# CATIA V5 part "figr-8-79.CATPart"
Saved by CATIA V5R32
Part number: Part1
Bounding box of the stored display mesh (mm): x -35 to 35, y -116.369 to 116.369, z 0 to 117.647
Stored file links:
  D:\PROJECTS\Project 2022\CATIA V5 6R 2022\Resources\Part Files\c08_catia_v5_6r2022_prt\figr-8-79.CATPart
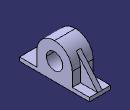
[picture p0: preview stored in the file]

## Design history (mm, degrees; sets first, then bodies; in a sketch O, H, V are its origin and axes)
Body1 (main body)
  Sketch1 on yz-plane, origin (0, 0, 0), H (0, 1, 0), V (0, 0, 1)
    line L1 (0, 0) -> (116.3687, 0)
    point P1 (116.3687, 0)
    line L2 (116.3687, 0) -> (116.3687, 12.5279)
    point P2 (116.3687, 12.5279)
    line L3 (116.3687, 12.5279) -> (58.943, 12.5279)
    point P3 (58.943, 12.5279)
    line L4 (58.943, 12.5279) -> (58.943, 58.7038)
    point P4 (58.943, 58.7038)
    arc A1 centre (0, 58.7038) radius 58.943 from (58.943, 58.7038) to (0, 117.6467) ccw
    point P5 (0, 58.7038)
    point P6 (-58.943, 58.7038)
    line L5 (-58.943, 58.7038) -> (-58.943, 12.5279)
    point P7 (-58.943, 12.5279)
    axis line L6 (0, 0) -> (0, 108.1111)
    point P9 (0, 117.6467)
    point P10 (0, 117.6467)
    point P11 (-58.943, 58.7038)
    arc A2 centre (0, 58.7038) radius 58.943 from (-58.943, 58.7038) to (0, 117.6467) cw
    point P13 (-58.943, 12.5279)
    point P14 (-116.3687, 12.5279)
    line L7 (-116.3687, 12.5279) -> (-58.943, 12.5279)
    point P15 (-116.3687, 0)
    line L8 (-116.3687, 0) -> (-116.3687, 12.5279)
    point P16 (0, 0)
    line L9 (0, 0) -> (-116.3687, 0)
    circle A3 centre (0, 58.7038) radius 27.1825
    horizontal: L1 H, L3 H
    vertical: L2 V, L4 V, L6 V
    tangency: A1 L4, L5 A1
    coincidence: P7 L3, P5 V, L6 P9, P6 P11, O P16, P9 P10, P7 P13
    symmetry: P9 P10 L6, P4 P11 L6, A1 A2 L6, P3 P13 L6, P2 P14 L6, L3 L7 L6, P1 P15 L6, L2 L8 L6, O P16 L6, L1 L9 L6
  Pad1: profile Sketch1, direction (1, 0, 0), length 35, mirrored extent
  Sketch2 on yz-plane, origin (0, 0, 0), H (0, 1, 0), V (0, 0, 1)
    line L1 (116.3687, 12.5279) -> (44.9741, 96.8037)
    point P1 (116.3687, 12.5279)
    point P2 (44.9741, 96.8037)
    reference projected arc E1 centre (0, 58.7038) radius 58.943 from (58.943, 58.7038) to (0, 117.6467) ccw from edge [face of Pad1 | face of Pad1]
    reference projected arc E2 centre (0, 58.7038) radius 58.943 from (58.943, 58.7038) to (0, 117.6467) ccw from edge [face of Pad1 | face of Pad1]
    reference projected point E3 (116.3687, 12.5279) from vertex [face of Pad1 | face of Pad1 | face of Pad1]
    tangency: L1 E1
    coincidence: P2 E2, P1 E3
  Stiffener1: ExtendedProfile Sketch2, ThicknessTop 0, ThicknessValue 15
